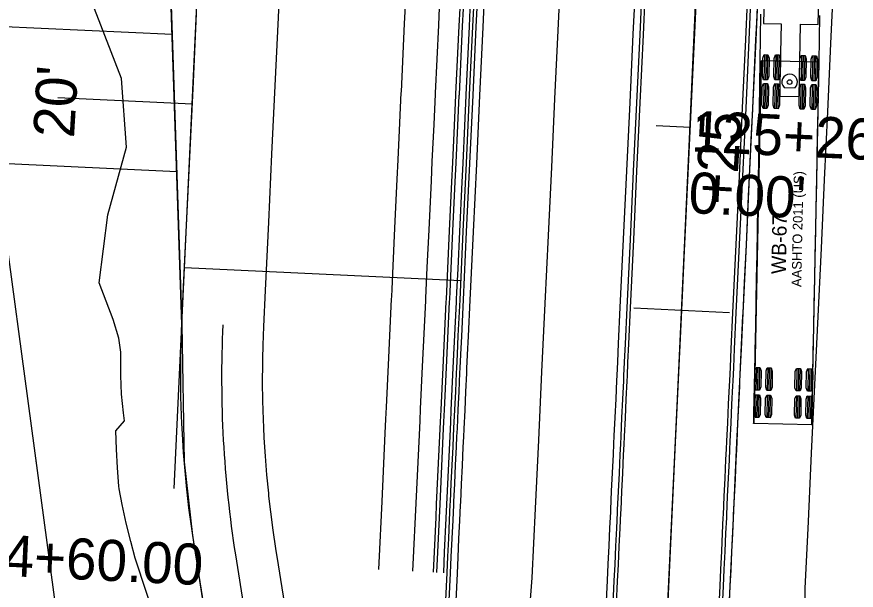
# Model space of a CAD drawing. Extents: x -70 to 701944, y -4 to 666871.
# Drawn here: x 668228 to 668350.9, y 655702.5 to 655786.4 of the extents above; entities that cross this region are included whole.
import ezdxf

# ---------------------------------------------------------------- set-up
doc = ezdxf.new("R2010")
doc.units = 0
for name, color, linetype in [('R_Draft', 7, 'Continuous'), ('R_Drive', 7, 'Continuous'), ('R_Erosion', 7, 'Continuous'), ('R_Horz Alg', 7, 'Continuous'), ('R_No Plot', 7, 'Continuous'), ('R_Proposed Const Limits', 7, 'Continuous'), ('R_Proposed Road', 7, 'Continuous'), ('R_ROW', 7, 'Continuous'), ('R_Striping', 7, 'Continuous'), ('T_Indications', 7, 'Continuous'), ('T_Notes', 7, 'Continuous'), ('T_Vehicle Path Lt Minor', 7, 'Continuous')]:
    doc.layers.add(name, color=color, linetype=linetype)

msp = doc.modelspace()

# ---------------------------------------------------------------- linework, layer by layer
at = {"layer": 'R_Draft'}
msp.add_lwpolyline([(668332.44, 655703.05), (668332.58, 655706.04), (668332.82, 655711.04), (668332.91, 655713.03), (668333.38, 655723.02), (668333.48, 655725.07), (668333.56, 655726.83), (668333.86, 655733.01), (668334.31, 655742.62), (668334.33, 655743), (668334.38, 655744.11), (668334.54, 655747.49), (668334.8, 655752.99), (668335.14, 655760.16), (668335.27, 655762.98), (668335.53, 655768.42), (668335.74, 655772.84), (668335.74, 655772.97), (668336.21, 655782.96), (668336.33, 655785.51), (668336.6, 655791.13)], dxfattribs=at)
at = {"layer": 'R_Drive'}
for p, q in [((668250.74, 655783.74), (668224.97, 655784.96)), ((668326.6, 655770.15), (668321.6, 655770.39)), ((668251.41, 655763.69), (668225.68, 655764.9)), ((668293.01, 655747.71), (668252.55, 655749.62))]:
    msp.add_line(p, q, dxfattribs=at)
at = {"layer": 'R_Erosion'}
msp.add_line((668252.16, 655741.35), (668249.93, 655808.13), dxfattribs=at)
at = {"layer": 'R_Horz Alg'}
msp.add_line((668254.91, 654251.16), (668327.61, 655791.56), dxfattribs=at)
msp.add_lwpolyline([(668318.35, 655743.76), (668332.33, 655743.1)], dxfattribs=at)
at = {"layer": 'R_No Plot'}
for p, q in [((668253.68, 655773.59), (668234.02, 655774.52)), ((668260, 655707.66), (668267.13, 655662.4))]:
    msp.add_line(p, q, dxfattribs=at)
for points in [[(668328.06, 655803.36), (668322.98, 655693.48), (668366.1, 655691.45), (668371.21, 655802.13), (668371.38, 655833.41), (668371.09, 655844.83), (668327.94, 655843.36), (668328.21, 655833.3)], [(668328.06, 655803.36), (668250.01, 655805.6), (668252.16, 655741.33), (668252.51, 655721.27), (668253.74, 655710.5), (668255.91, 655696.65), (668322.98, 655693.48), (668325.34, 655743.43)]]:
    msp.add_lwpolyline(points, close=True, dxfattribs=at)
msp.add_arc((668423.98, 655733.49), 166, 177.2978, 188.9514, dxfattribs=at)
at = {"layer": 'R_Proposed Const Limits'}
msp.add_lwpolyline([(668248.69, 655696.99), (668245.32, 655707.16), (668244.7, 655709.59), (668244.03, 655712.29), (668243.4, 655714.99), (668242.96, 655717.28), (668242.93, 655717.69), (668242.74, 655720.39), (668242.6, 655723.09), (668242.5, 655725.79), (668243.74, 655727.25), (668243.61, 655728.44), (668243.34, 655731.16), (668243.22, 655733.88), (668243.23, 655736.59), (668243.24, 655737.29), (668242.95, 655739.32), (668242.11, 655742.07), (668240.06, 655747.45), (668241.32, 655757.4), (668244.07, 655767.28), (668243.33, 655777.33), (668239.37, 655787.53)], dxfattribs=at)
at = {"layer": 'R_Proposed Road'}
for points in [[(668267.9, 655696.08), (668266.31, 655706.17), (668265.93, 655708.59), (668265.53, 655711.27), (668265.18, 655713.96), (668264.91, 655716.24), (668264.87, 655716.66), (668264.61, 655719.36), (668264.39, 655722.06), (668264.22, 655724.77), (668264.14, 655726.29), (668264.1, 655727.47), (668264.02, 655730.19), (668263.98, 655732.9), (668264, 655735.61), (668264.01, 655736.31), (668264.06, 655738.32), (668264.16, 655741.03), (668264.41, 655746.3), (668264.88, 655756.29), (668265.35, 655766.28), (668265.82, 655776.27), (668266.29, 655786.26), (668266.56, 655791.84)], [(668290.52, 655695.01), (668290.99, 655705), (668291.1, 655707.4), (668291.23, 655710.06), (668291.36, 655712.73), (668291.46, 655714.99), (668291.48, 655715.4), (668291.61, 655718.08), (668291.74, 655720.77), (668291.86, 655723.46), (668291.93, 655724.98), (668291.99, 655726.16), (668292.12, 655728.86), (668292.25, 655731.56), (668292.37, 655734.27), (668292.41, 655734.97), (668292.5, 655736.98), (668292.63, 655739.69), (668292.88, 655744.96), (668293.35, 655754.95), (668293.82, 655764.93), (668294.29, 655774.92), (668294.76, 655784.91), (668295.03, 655790.5)], [(668291.02, 655694.99), (668291.49, 655704.98), (668291.6, 655707.38), (668291.73, 655710.04), (668291.86, 655712.7), (668291.96, 655714.97), (668291.98, 655715.38), (668292.11, 655718.06), (668292.24, 655720.75), (668292.36, 655723.44), (668292.43, 655724.96), (668292.49, 655726.13), (668292.62, 655728.84), (668292.74, 655731.54), (668292.87, 655734.25), (668292.91, 655734.94), (668293, 655736.95), (668293.13, 655739.66), (668293.38, 655744.93), (668293.85, 655754.92), (668294.32, 655764.91), (668294.79, 655774.9), (668295.26, 655784.89), (668295.53, 655790.47)], [(668292.02, 655694.94), (668292.49, 655704.93), (668292.6, 655707.33), (668292.73, 655709.99), (668292.85, 655712.66), (668292.96, 655714.92), (668292.98, 655715.33), (668293.11, 655718.01), (668293.23, 655720.7), (668293.36, 655723.39), (668293.43, 655724.91), (668293.49, 655726.09), (668293.62, 655728.79), (668293.74, 655731.49), (668293.87, 655734.2), (668293.9, 655734.9), (668294, 655736.91), (668294.13, 655739.62), (668294.38, 655744.89), (668294.85, 655754.88), (668295.32, 655764.86), (668295.79, 655774.85), (668296.26, 655784.84), (668296.52, 655790.43)], [(668313.99, 655693.9), (668314.47, 655703.89), (668314.58, 655706.3), (668314.7, 655708.95), (668314.83, 655711.62), (668314.94, 655713.88), (668314.96, 655714.29), (668315.08, 655716.97), (668315.21, 655719.66), (668315.34, 655722.35), (668315.41, 655723.87), (668315.46, 655725.05), (668315.59, 655727.75), (668315.72, 655730.46), (668315.85, 655733.16), (668315.88, 655733.86), (668315.97, 655735.87), (668316.1, 655738.58), (668316.35, 655743.85), (668316.82, 655753.84), (668317.29, 655763.83), (668317.77, 655773.82), (668318.24, 655783.8), (668318.5, 655789.39)], [(668314.99, 655693.86), (668315.46, 655703.85), (668315.58, 655706.25), (668315.7, 655708.91), (668315.83, 655711.57), (668315.94, 655713.84), (668315.95, 655714.25), (668316.08, 655716.93), (668316.21, 655719.61), (668316.34, 655722.31), (668316.41, 655723.82), (668316.46, 655725), (668316.59, 655727.7), (668316.72, 655730.41), (668316.85, 655733.11), (668316.88, 655733.81), (668316.97, 655735.82), (668317.1, 655738.53), (668317.35, 655743.8), (668317.82, 655753.79), (668318.29, 655763.78), (668318.76, 655773.77), (668319.24, 655783.76), (668319.5, 655789.34)], [(668315.49, 655693.83), (668315.96, 655703.82), (668316.08, 655706.22), (668316.2, 655708.88), (668316.33, 655711.55), (668316.44, 655713.81), (668316.45, 655714.22), (668316.58, 655716.9), (668316.71, 655719.59), (668316.83, 655722.28), (668316.91, 655723.8), (668316.96, 655724.98), (668317.09, 655727.68), (668317.22, 655730.38), (668317.34, 655733.09), (668317.38, 655733.79), (668317.47, 655735.8), (668317.6, 655738.51), (668317.85, 655743.78), (668318.32, 655753.77), (668318.79, 655763.76), (668319.26, 655773.75), (668319.74, 655783.73), (668320, 655789.32)], [(668330.48, 655693.13), (668330.95, 655703.12), (668331.06, 655705.52), (668331.19, 655708.18), (668331.31, 655710.84), (668331.42, 655713.1), (668331.44, 655713.51), (668331.56, 655716.2), (668331.69, 655718.88), (668331.82, 655721.58), (668331.89, 655723.09), (668331.95, 655724.27), (668332.07, 655726.97), (668332.2, 655729.68), (668332.33, 655732.38), (668332.36, 655733.08), (668332.46, 655735.09), (668332.58, 655737.8), (668332.83, 655743.07), (668333.3, 655753.06), (668333.78, 655763.05), (668334.25, 655773.04), (668334.72, 655783.03), (668334.98, 655788.61)], [(668330.97, 655693.1), (668331.45, 655703.09), (668331.56, 655705.49), (668331.69, 655708.15), (668331.81, 655710.82), (668331.92, 655713.08), (668331.94, 655713.49), (668332.06, 655716.17), (668332.19, 655718.86), (668332.32, 655721.55), (668332.39, 655723.07), (668332.44, 655724.25), (668332.57, 655726.95), (668332.7, 655729.65), (668332.83, 655732.36), (668332.86, 655733.06), (668332.96, 655735.07), (668333.08, 655737.78), (668333.33, 655743.05), (668333.8, 655753.04), (668334.28, 655763.03), (668334.75, 655773.01), (668335.22, 655783), (668335.48, 655788.59)], [(668331.97, 655693.06), (668332.45, 655703.05), (668332.56, 655705.45), (668332.68, 655708.1), (668332.81, 655710.77), (668332.92, 655713.03), (668332.94, 655713.44), (668333.06, 655716.13), (668333.19, 655718.81), (668333.32, 655721.5), (668333.39, 655723.02), (668333.44, 655724.2), (668333.57, 655726.9), (668333.7, 655729.61), (668333.83, 655732.31), (668333.86, 655733.01), (668333.95, 655735.02), (668334.08, 655737.73), (668334.33, 655743), (668334.8, 655752.99), (668335.27, 655762.98), (668335.75, 655772.97), (668336.22, 655782.96), (668336.48, 655788.54)], [(668255.91, 655696.65), (668254.33, 655706.73), (668253.94, 655709.16), (668253.55, 655711.84), (668253.19, 655714.53), (668252.93, 655716.81), (668252.88, 655717.22), (668252.62, 655719.92), (668252.4, 655722.62), (668252.23, 655725.33), (668252.16, 655726.86), (668252.11, 655728.04), (668252.03, 655730.75), (668252, 655733.46), (668252.01, 655736.17), (668252.02, 655736.87), (668252.07, 655738.89), (668252.17, 655741.6), (668252.42, 655746.87), (668252.89, 655756.86), (668253.37, 655766.84), (668253.84, 655776.83), (668254.31, 655786.82)]]:
    msp.add_lwpolyline(points, dxfattribs=at)
at = {"layer": 'R_ROW'}
msp.add_lwpolyline([(668212.48, 655027.95), (668191.19, 655107.04), (668183.46, 655282.6), (668195.34, 655301.06), (668198.49, 655389.01), (668237.93, 655482.26), (668241.48, 655642.27), (668225.92, 655758.13), (668224.14, 655808.01), (668090.41, 656138.46), (668097.37, 656215.3), (668068.22, 656367.07)], dxfattribs=at)
at = {"layer": 'R_Striping'}
for points in [[(668296.51, 655614.33), (668297.28, 655624.3), (668298.05, 655634.28), (668298.63, 655641.82), (668298.82, 655644.25), (668299.59, 655654.23), (668300.36, 655664.2), (668301.13, 655674.18), (668301.9, 655684.15), (668302.68, 655694.13), (668303.46, 655704.27), (668303.94, 655714.42), (668304.41, 655724.41), (668304.88, 655734.4), (668305.35, 655744.39), (668305.82, 655754.38), (668306.3, 655764.37), (668306.77, 655774.36), (668307.24, 655784.35), (668307.63, 655792.54)], [(668341.88, 655612.85), (668342.06, 655622.85), (668342.23, 655632.85), (668342.36, 655640.42), (668342.4, 655642.86), (668342.57, 655652.86), (668342.74, 655662.86), (668342.92, 655672.87), (668343.09, 655682.87), (668343.26, 655692.87), (668343.43, 655702.71), (668343.89, 655712.54), (668344.36, 655722.53), (668344.83, 655732.52), (668345.31, 655742.5), (668345.78, 655752.49), (668346.25, 655762.48), (668346.72, 655772.47), (668347.19, 655782.46), (668347.58, 655790.66)]]:
    msp.add_lwpolyline(points, dxfattribs=at)
at = {"layer": 'T_Indications'}
for points in [[(668281, 655705.48), (668281.14, 655708.46), (668281.38, 655713.46), (668281.47, 655715.46), (668281.94, 655725.45), (668282.04, 655727.5), (668282.12, 655729.25), (668282.41, 655735.44), (668282.87, 655745.04), (668282.88, 655745.43), (668282.94, 655746.53), (668283.1, 655749.92), (668283.36, 655755.42), (668283.69, 655762.59), (668283.83, 655765.41), (668284.08, 655770.85), (668284.29, 655775.27), (668284.3, 655775.4), (668284.77, 655785.38), (668284.89, 655787.94), (668285.16, 655793.56)], [(668285.99, 655705.24), (668286.13, 655708.23), (668286.37, 655713.23), (668286.46, 655715.23), (668286.94, 655725.22), (668287.03, 655727.26), (668287.12, 655729.02), (668287.41, 655735.2), (668287.86, 655744.81), (668287.88, 655745.19), (668287.93, 655746.3), (668288.09, 655749.68), (668288.35, 655755.18), (668288.69, 655762.36), (668288.82, 655765.17), (668289.08, 655770.61), (668289.29, 655775.03), (668289.29, 655775.16), (668289.76, 655785.15), (668289.89, 655787.7), (668290.15, 655793.33)], [(668288.99, 655705.1), (668289.13, 655708.09), (668289.37, 655713.09), (668289.46, 655715.08), (668289.93, 655725.07), (668290.03, 655727.12), (668290.11, 655728.88), (668290.4, 655735.06), (668290.86, 655744.67), (668290.88, 655745.05), (668290.93, 655746.16), (668291.09, 655749.54), (668291.35, 655755.04), (668291.69, 655762.21), (668291.82, 655765.03), (668292.08, 655770.47), (668292.28, 655774.89), (668292.29, 655775.02), (668292.76, 655785.01), (668292.88, 655787.56), (668293.15, 655793.18)], [(668289.49, 655705.08), (668289.63, 655708.06), (668289.87, 655713.06), (668289.96, 655715.06), (668290.43, 655725.05), (668290.53, 655727.1), (668290.61, 655728.85), (668290.9, 655735.04), (668291.36, 655744.64), (668291.38, 655745.03), (668291.43, 655746.13), (668291.59, 655749.52), (668291.85, 655755.02), (668292.19, 655762.19), (668292.32, 655765.01), (668292.57, 655770.44), (668292.78, 655774.86), (668292.79, 655774.99), (668293.26, 655784.98), (668293.38, 655787.54), (668293.65, 655793.16)], [(668290.49, 655705.03), (668290.63, 655708.02), (668290.87, 655713.02), (668290.96, 655715.01), (668291.43, 655725), (668291.53, 655727.05), (668291.61, 655728.81), (668291.9, 655734.99), (668292.36, 655744.6), (668292.37, 655744.98), (668292.43, 655746.09), (668292.59, 655749.47), (668292.85, 655754.97), (668293.18, 655762.14), (668293.32, 655764.96), (668293.57, 655770.4), (668293.78, 655774.82), (668293.79, 655774.95), (668294.26, 655784.94), (668294.38, 655787.49), (668294.65, 655793.11)], [(668332.01, 655693.84), (668332.44, 655703.05), (668332.58, 655706.04), (668332.82, 655711.04), (668332.91, 655713.03), (668333.38, 655723.02), (668333.48, 655725.07), (668333.56, 655726.83), (668333.86, 655733.01), (668334.31, 655742.62), (668334.33, 655743), (668334.38, 655744.11), (668334.54, 655747.49), (668334.8, 655752.99), (668335.14, 655760.16), (668335.27, 655762.98), (668335.53, 655768.42), (668335.74, 655772.84), (668335.74, 655772.97), (668336.21, 655782.96), (668336.33, 655785.51), (668336.6, 655791.13)]]:
    msp.add_lwpolyline(points, dxfattribs=at)
at = {"layer": 'T_Notes'}
msp.add_line((668251.03, 655717.35), (668257.92, 655863.25), dxfattribs=at)
at = {"layer": 'T_Vehicle Path Lt Minor'}
for p, q in [((668337.62, 655800.38), (668337.32, 655785.39)), ((668345.31, 655785.22), (668345.62, 655800.22)), ((668337.32, 655785.39), (668339.88, 655785.33)), ((668339.88, 655785.33), (668339.67, 655774.74)), ((668342.53, 655774.68), (668342.75, 655785.28)), ((668342.75, 655785.28), (668345.31, 655785.22)), ((668337.45, 655780.82), (668337.38, 655777.15)), ((668337.68, 655780.81), (668337.61, 655777.14)), ((668337.91, 655780.81), (668337.84, 655777.14)), ((668339.1, 655780.78), (668339.03, 655777.12)), ((668339.33, 655780.78), (668339.26, 655777.11)), ((668339.56, 655780.77), (668339.49, 655777.11)), ((668342.89, 655780.71), (668342.81, 655777.04)), ((668343.11, 655780.7), (668343.04, 655777.03)), ((668343.34, 655780.7), (668343.27, 655777.03)), ((668344.53, 655780.67), (668344.46, 655777.01)), ((668344.76, 655780.67), (668344.69, 655777)), ((668344.99, 655780.66), (668344.92, 655777)), ((668336.95, 655779.89), (668335.88, 655726.9)), ((668345.45, 655779.72), (668336.95, 655779.89)), ((668336.95, 655779.89), (668336.95, 655779.89)), ((668344.38, 655726.73), (668345.45, 655779.72)), ((668337.37, 655776.62), (668337.29, 655772.95)), ((668337.6, 655776.61), (668337.52, 655772.95)), ((668337.83, 655776.61), (668337.75, 655772.94)), ((668339.02, 655776.58), (668338.94, 655772.92)), ((668339.25, 655776.58), (668339.17, 655772.91)), ((668339.48, 655776.57), (668339.4, 655772.91)), ((668340.32, 655776.01), (668341.93, 655775.98)), ((668342.8, 655776.51), (668342.73, 655772.84)), ((668343.03, 655776.5), (668342.95, 655772.84)), ((668343.26, 655776.5), (668343.18, 655772.83)), ((668344.45, 655776.47), (668344.38, 655772.81)), ((668344.68, 655776.47), (668344.6, 655772.8)), ((668344.91, 655776.46), (668344.83, 655772.8)), ((668339.67, 655774.74), (668342.53, 655774.68)), ((668336.28, 655735.05), (668336.21, 655731.75)), ((668336.5, 655735.04), (668336.44, 655731.74)), ((668336.73, 655735.04), (668336.67, 655731.74)), ((668337.93, 655735.01), (668337.86, 655731.71)), ((668338.15, 655735.01), (668338.09, 655731.71)), ((668338.38, 655735), (668338.32, 655731.7)), ((668342.21, 655734.93), (668342.14, 655731.63)), ((668342.44, 655734.92), (668342.37, 655731.62)), ((668342.67, 655734.92), (668342.6, 655731.62)), ((668343.86, 655734.89), (668343.79, 655731.59)), ((668344.09, 655734.89), (668344.02, 655731.59)), ((668344.32, 655734.88), (668344.25, 655731.58)), ((668336.19, 655731.05), (668336.13, 655727.75)), ((668336.42, 655731.04), (668336.36, 655727.74)), ((668336.65, 655731.04), (668336.59, 655727.74)), ((668337.84, 655731.01), (668337.78, 655727.71)), ((668338.07, 655731.01), (668338.01, 655727.71)), ((668338.3, 655731), (668338.24, 655727.71)), ((668342.13, 655730.93), (668342.06, 655727.63)), ((668342.36, 655730.92), (668342.29, 655727.62)), ((668342.59, 655730.92), (668342.52, 655727.62)), ((668343.78, 655730.89), (668343.71, 655727.59)), ((668344.01, 655730.89), (668343.94, 655727.59)), ((668344.23, 655730.88), (668344.17, 655727.59)), ((668335.88, 655726.9), (668344.38, 655726.73))]:
    msp.add_line(p, q, dxfattribs=at)
for points in [[(668335.88, 655726.9), (668335.95, 655730.44), (668336.02, 655733.97), (668336.1, 655737.5), (668336.17, 655741.03), (668336.24, 655744.57), (668336.3, 655748.1), (668336.37, 655751.63), (668336.44, 655755.16), (668336.5, 655758.7), (668336.56, 655762.23), (668336.62, 655765.76), (668336.67, 655769.3), (668336.73, 655772.83), (668336.78, 655776.36), (668336.82, 655779.89), (668336.87, 655783.31), (668336.9, 655786.73)], [(668344.38, 655726.73), (668344.45, 655730.26), (668344.52, 655733.8), (668344.59, 655737.33), (668344.67, 655740.86), (668344.74, 655744.39), (668344.81, 655747.93), (668344.88, 655751.46), (668344.95, 655754.99), (668345.02, 655758.52), (668345.1, 655762.06), (668345.17, 655765.59), (668345.24, 655769.12), (668345.31, 655772.65), (668345.38, 655776.19), (668345.45, 655779.72), (668345.45, 655779.72), (668345.52, 655783.14), (668345.58, 655786.55)]]:
    msp.add_lwpolyline(points, dxfattribs=at)
for points in [[(668337.4, 655780.82), (668337.97, 655780.8), (668338.13, 655780.29), (668338.08, 655777.65), (668337.89, 655777.14), (668337.32, 655777.15), (668337.16, 655777.67), (668337.21, 655780.31)], [(668339.05, 655780.78), (668339.62, 655780.77), (668339.78, 655780.25), (668339.73, 655777.62), (668339.54, 655777.11), (668338.97, 655777.12), (668338.81, 655777.63), (668338.86, 655780.27)], [(668342.83, 655780.71), (668343.4, 655780.69), (668343.56, 655780.18), (668343.51, 655777.54), (668343.33, 655777.03), (668342.75, 655777.04), (668342.59, 655777.56), (668342.65, 655780.2)], [(668344.48, 655780.67), (668345.05, 655780.66), (668345.21, 655780.14), (668345.16, 655777.51), (668344.98, 655777), (668344.4, 655777.01), (668344.24, 655777.52), (668344.3, 655780.16)], [(668337.31, 655776.62), (668337.88, 655776.61), (668338.04, 655776.09), (668337.99, 655773.45), (668337.81, 655772.94), (668337.24, 655772.95), (668337.07, 655773.47), (668337.13, 655776.11)], [(668338.96, 655776.58), (668339.53, 655776.57), (668339.69, 655776.06), (668339.64, 655773.42), (668339.46, 655772.91), (668338.89, 655772.92), (668338.72, 655773.43), (668338.78, 655776.07)], [(668342.74, 655776.51), (668343.32, 655776.5), (668343.48, 655775.98), (668343.42, 655773.34), (668343.24, 655772.83), (668342.67, 655772.84), (668342.51, 655773.36), (668342.56, 655776)], [(668344.39, 655776.47), (668344.96, 655776.46), (668345.13, 655775.95), (668345.07, 655773.31), (668344.89, 655772.8), (668344.32, 655772.81), (668344.16, 655773.32), (668344.21, 655775.96)], [(668336.22, 655735.05), (668336.79, 655735.04), (668336.95, 655734.57), (668336.91, 655732.2), (668336.72, 655731.74), (668336.15, 655731.75), (668335.99, 655732.21), (668336.04, 655734.59)], [(668337.87, 655735.01), (668338.44, 655735), (668338.6, 655734.54), (668338.56, 655732.16), (668338.37, 655731.7), (668337.8, 655731.71), (668337.64, 655732.18), (668337.69, 655734.56)], [(668342.15, 655734.93), (668342.72, 655734.92), (668342.89, 655734.45), (668342.84, 655732.07), (668342.66, 655731.62), (668342.08, 655731.63), (668341.92, 655732.09), (668341.97, 655734.47)], [(668343.8, 655734.89), (668344.37, 655734.88), (668344.54, 655734.42), (668344.49, 655732.04), (668344.31, 655731.58), (668343.73, 655731.59), (668343.57, 655732.06), (668343.62, 655734.44)], [(668336.14, 655731.05), (668336.71, 655731.04), (668336.87, 655730.57), (668336.82, 655728.2), (668336.64, 655727.74), (668336.07, 655727.75), (668335.91, 655728.21), (668335.96, 655730.59)], [(668337.79, 655731.02), (668338.36, 655731), (668338.52, 655730.54), (668338.47, 655728.16), (668338.29, 655727.7), (668337.72, 655727.72), (668337.56, 655728.18), (668337.61, 655730.56)], [(668342.07, 655730.93), (668342.64, 655730.92), (668342.8, 655730.45), (668342.76, 655728.08), (668342.58, 655727.62), (668342, 655727.63), (668341.84, 655728.09), (668341.89, 655730.47)], [(668343.72, 655730.89), (668344.29, 655730.88), (668344.45, 655730.42), (668344.41, 655728.04), (668344.22, 655727.58), (668343.65, 655727.6), (668343.49, 655728.06), (668343.54, 655730.44)]]:
    msp.add_lwpolyline(points, close=True, dxfattribs=at)
for centre, radius in [((668341.14, 655776.81), 0.34), ((668335.88, 655726.9), 0.0417), ((668344.38, 655726.73), 0.0417)]:
    msp.add_circle(centre, radius, dxfattribs=at)
msp.add_arc((668341.14, 655776.81), 1.14, 313.8397, 223.8397, dxfattribs=at)

# ---------------------------------------------------------------- texts
at = {"layer": 'R_Drive'}
for s, p in [("20'", (668236.36, 655768.53)), ('+25', (668333.28, 655758.7))]:
    msp.add_text(s, height=6, rotation=86.5585, dxfattribs=at).set_placement(p)
at = {"layer": 'R_No Plot'}
for s, height, rotation, p in [('125+26.75 ', 6, 357.2978, (668326.67, 655766.65)), ('+', 0.1, 87.2978, (668326.61, 655769.35)), ('+', 0.1, 87.2978, (668326.57, 655768.35)), ("0.00' ", 6, 357.2978, (668326.25, 655757.66)), ('124+60.00 ', 6, 357.2978, (668217.03, 655705))]:
    msp.add_text(s, height=height, rotation=rotation, dxfattribs=at).set_placement(p)
at = {"layer": 'T_Vehicle Path Lt Minor'}
for s, height, p in [('AASHTO 2011 (US)', 1.4167, (668342.84, 655746.82)), ('WB-67', 2.125, (668340.57, 655748.69))]:
    msp.add_text(s, height=height, rotation=88.8397, dxfattribs=at).set_placement(p)

doc.saveas('drawing.dxf')
